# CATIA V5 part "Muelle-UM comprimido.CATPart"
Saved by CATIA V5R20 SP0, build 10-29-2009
Part number: Muelle-UM comprimido
Revision: ANY
Definition: UNKNOWN
Nomenclature: Muelle-UM comprimido
Source: Unknown
Bounding box of the stored display mesh (mm): x -1.2 to 1.2, y -1.2 to 1.2, z -0.001 to 4
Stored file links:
  C:\Users\Utente\Desktop\IO LAVORO\3D X SITO CF\X SITO\3D files UM\UM043642 PRODUCT\Muelle-UM comprimido.CATPart
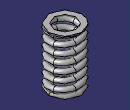
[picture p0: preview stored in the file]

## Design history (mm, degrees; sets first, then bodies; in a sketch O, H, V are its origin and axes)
Body1 "Cortar-Extruir1" (main body)
  Solid1: solid without history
